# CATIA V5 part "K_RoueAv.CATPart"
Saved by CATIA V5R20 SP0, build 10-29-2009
Part number: roue_avant
Publications: "Corps principal", "niveau de la roue avant", "hauteur roue avant", "Point.1", "Droite.1", "Droite.2", "Droite.3", "Droite.4", "Droite.5"
Bounding box of the stored display mesh (mm): x 800 to 900, y -50 to 0, z -150 to -50
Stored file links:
  G:\Khaled_CFAO_2011\ST2M\ST2M_GR1\cdurantin\cdurantin\Khaled\CAD_ThinkMOTION\K_RoueAv.CATPart
  G:\Khaled_CFAO_2011\ST2M\ST2M_GR1\cdurantin\cdurantin\Khaled\CAD_ThinkMOTION\K_Corps.CATPart
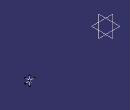
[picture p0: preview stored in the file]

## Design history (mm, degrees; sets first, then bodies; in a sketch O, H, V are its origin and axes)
External parameters (linked from other documents)
  `External.niveau de la roue avant` = 850 mm
  `External.hauteur roue avant` = 100 mm
Body1 (main body)
  Point1: (850 {= `External.niveau de la roue avant`}, 0, -100 {= -`External.hauteur roue avant`})
  Line1: type PtDir, RefPoint Point1, Direction zx-plane, Start 0, End -50
  Line2: type PtDir, RefPoint Point1, Direction xy-plane, Start 0, End -50
  Line3: type PtDir, RefPoint Point1, Direction xy-plane, Start 0, End 50
  Line4: type Normal, RefPoint Point1, RefSkin yz-plane, Start 0, End 50
  Line5: type PtDir, RefPoint Point1, Direction yz-plane, Start 0, End -50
